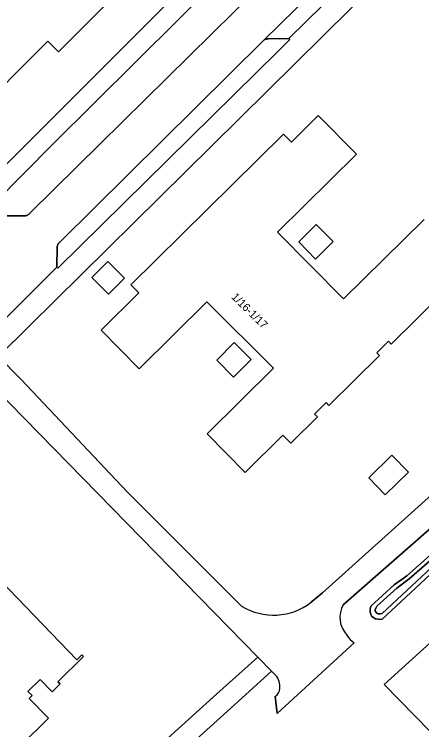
# Model space of a CAD drawing. Extents: x 162788 to 163838, y 385791 to 386523.
# Drawn here: x 163092.2 to 163143.1, y 386015.9 to 386105.3 of the extents above; entities that cross this region are included whole.
import ezdxf

# ---------------------------------------------------------------- set-up
doc = ezdxf.new("R2010")
doc.units = 0
for name, color, linetype in [('IMGEO_Berm_groen', 7, 'Continuous'), ('IMGEO_Erf', 7, 'Continuous'), ('IMGEO_Grasland_overig', 7, 'Continuous'), ('IMGEO_Groenvoorziening', 7, 'Continuous'), ('IMGEO_Hek', 7, 'Continuous'), ('IMGEO_Oever', 7, 'Continuous'), ('IMGEO_Pand', 7, 'Continuous'), ('IMGEO_Pand_nummerreeks', 7, 'Continuous'), ('IMGEO_Parkeervlak_open', 7, 'Continuous'), ('IMGEO_Rijbaan_lokaal_gesloten', 7, 'Continuous'), ('IMGEO_Voetpad_halfverhard', 7, 'Continuous'), ('IMGEO_Waterloop', 7, 'Continuous'), ('IMGEO_Woonerf_gesloten', 7, 'Continuous'), ('IMGEO_Woonerf_open', 7, 'Continuous')]:
    doc.layers.add(name, color=color, linetype=linetype)

msp = doc.modelspace()

# ---------------------------------------------------------------- linework, layer by layer
at = {"layer": 'IMGEO_Berm_groen'}
for points in [[(163117.963, 386109.833), (163097.035, 386089.065), (163082.472, 386074.358)], [(163091.029, 386080.088), (163093.415, 386080.108), (163093.492, 386080.104), (163093.569, 386080.106), (163093.646, 386080.114), (163093.721, 386080.13), (163093.795, 386080.151), (163093.867, 386080.179), (163093.937, 386080.212), (163094.003, 386080.252), (163094.066, 386080.296), (163094.124, 386080.346), (163094.179, 386080.401), (163094.228, 386080.46), (163102.959, 386089.088), (163122.487, 386108.369)]]:
    msp.add_lwpolyline(points, dxfattribs=at)
msp.add_lwpolyline([(163125.212, 386100.685), (163126.659, 386102.115), (163126.525, 386102.25), (163123.979, 386102.211), (163123.89, 386102.211), (163123.802, 386102.203), (163123.714, 386102.186), (163123.629, 386102.162), (163123.546, 386102.129), (163123.467, 386102.089), (163123.392, 386102.042), (163097.956, 386076.871), (163097.891, 386076.815), (163097.831, 386076.753), (163097.776, 386076.687), (163097.728, 386076.616), (163097.685, 386076.542), (163097.648, 386076.464), (163097.618, 386076.383), (163097.595, 386076.301), (163097.579, 386076.216), (163097.552, 386073.701), (163097.687, 386073.563)], close=True, dxfattribs=at)
at = {"layer": 'IMGEO_Erf'}
for points in [[(163047.932, 386111.375), (163063.284, 386095.753), (163064.785, 386094.225), (163081.598, 386077.116), (163079.514, 386075.045), (163075.814, 386078.831), (163062.665, 386092.122), (163061.26, 386090.73), (163077.652, 386074.193), (163078.625, 386073.903), (163090.945, 386086.246), (163109.567, 386104.883), (163137.817, 386133.231)], [(163144.69, 386116.333), (163116.889, 386088.826), (163094.139, 386066.379), (163090.229, 386062.548), (163093.084, 386059.675), (163106.347, 386045.615), (163117.907, 386034.052), (163120.625, 386031.361)], [(163105.221, 386108.078), (163097.748, 386100.603), (163096.425, 386101.925), (163086.649, 386092.147), (163084.686, 386094.11), (163079.63, 386089.054), (163076.992, 386091.691), (163076.292, 386090.991), (163073.29, 386093.993), (163073.99, 386094.693), (163069.539, 386099.143), (163070.229, 386099.833), (163068.902, 386101.16), (163068.212, 386100.47), (163060.737, 386107.943)], [(163145.83, 386070.54), (163139.3, 386064.088), (163138.953, 386064.438), (163137.507, 386063.009), (163137.853, 386062.658), (163131.536, 386056.417), (163131.19, 386056.767), (163129.743, 386055.338), (163130.09, 386054.987), (163126.763, 386051.7), (163125.779, 386052.696), (163121.082, 386048.054), (163116.31, 386052.871), (163124.617, 386061.079), (163116.284, 386069.342), (163107.849, 386061.007), (163103.083, 386065.83), (163107.785, 386070.475), (163106.801, 386071.471), (163125.865, 386090.318), (163126.854, 386089.317), (163130.198, 386092.621), (163134.963, 386087.798), (163125.119, 386078.071), (163133.366, 386069.724), (163143.424, 386079.662)], [(163129.316, 386031.834), (163130.711, 386032.995), (163156.731, 386056.38), (163168.437, 386066.688), (163193.001, 386088.975)], [(163122.643, 386025), (163088.018, 386060.382), (163078.994, 386051.539), (163082.592, 386051.498)], [(163083.877, 386047.013), (163077.501, 386040.771), (163078.117, 386040.121), (163082.342, 386044.263), (163082.601, 386043.999), (163081.98, 386043.39), (163100.049, 386024.635), (163100.685, 386025.264), (163100.884, 386025.064), (163097.686, 386021.901), (163097.949, 386021.634), (163096.965, 386020.661), (163095.449, 386022.194), (163093.939, 386020.701), (163094.444, 386020.19), (163094.075, 386019.826), (163096.492, 386017.373), (163085.965, 386006.999)], [(163017.319, 385930.66), (163017.729, 385931.02), (163049.154, 385958.577), (163094.983, 386000), (163117.539, 386020.387), (163122.643, 386025)]]:
    msp.add_lwpolyline(points, dxfattribs=at)
for points in [[(163132.041, 386076.88), (163129.874, 386074.708), (163127.777, 386076.862), (163129.94, 386079.033)], [(163101.922, 386072.392), (163103.931, 386074.377), (163105.989, 386072.295), (163103.98, 386070.31)], [(163121.809, 386062.144), (163119.615, 386059.957), (163117.538, 386062.084), (163119.713, 386064.262)], [(163141.454, 386048.102), (163138.549, 386045.273), (163136.502, 386047.374), (163139.407, 386050.204)]]:
    msp.add_lwpolyline(points, close=True, dxfattribs=at)
msp.add_arc((163124.628, 386037.886), 7.655, 238.4692, 307.7612, dxfattribs=at)
at = {"layer": 'IMGEO_Grasland_overig'}
for points in [[(163105.896, 385959.534), (163111.404, 385963.758), (163130.396, 385976.293), (163134.062, 385978.713), (163159.928, 385999.607), (163159.543, 386000), (163138.447, 386021.548), (163206.371, 386083.102), (163206.676, 386083.379), (163205.132, 386083.984), (163204.985, 386084.042), (163200.984, 386088.924), (163199.323, 386090.951), (163185.549, 386078.284), (163151.762, 386047.67), (163133.296, 386031.516)], [(163153.289, 386044.004), (163148.997, 386039.8), (163138.145, 386029.699), (163137.723, 386029.721), (163137.336, 386029.787), (163136.909, 386030.048), (163136.805, 386030.22), (163136.703, 386030.604), (163136.703, 386030.967), (163136.754, 386031.335), (163139.702, 386033.993), (163141.245, 386035.148), (163145.656, 386039.012), (163151.533, 386044.911), (163153.619, 386046.984), (163166.13, 386058.037), (163180.769, 386071.382), (163186.623, 386076.52), (163193.122, 386082.894), (163194.705, 386084.249), (163196.048, 386085.124)], [(163134.7, 386026.782), (163125.061, 386017.943), (163124.832, 386020.084)], [(163124.87, 386022.725), (163124.372, 386023.234), (163119.271, 386018.624), (163098.66, 386000), (163052.327, 385958.135), (163019.493, 385929.004)]]:
    msp.add_lwpolyline(points, dxfattribs=at)
for centre, radius, start, end in [((163136.215, 386029.958), 3.309, 151.90734, 222.69125), ((163136.2, 386029.175), 2.824, 211.14826, 237.92213), ((163123.263, 386021.308), 2.142, 353.61215, 41.39921), ((163124.063, 386021.173), 1.333, 305.23176, 355.57931)]:
    msp.add_arc(centre, radius, start, end, dxfattribs=at)
at = {"layer": 'IMGEO_Groenvoorziening'}
msp.add_lwpolyline([(163250.444, 386051.706), (163235.031, 386068.8), (163224.12, 386071.151), (163212.227, 386083.36), (163211.761, 386083.838), (163211.088, 386083.548), (163209.338, 386081.658), (163206.676, 386083.379), (163206.371, 386083.102), (163138.447, 386021.548), (163159.543, 386000), (163159.928, 385999.607), (163178.242, 386000), (163195.252, 386000.365)], close=True, dxfattribs=at)
at = {"layer": 'IMGEO_Hek'}
msp.add_lwpolyline([(163159.928, 385999.607), (163159.543, 386000), (163138.447, 386021.548), (163206.371, 386083.102), (163209.628, 386080.994), (163212.227, 386083.36)], dxfattribs=at)
at = {"layer": 'IMGEO_Oever'}
for points in [[(163148.646, 386040.168), (163138.178, 386030.424), (163137.93, 386030.383), (163137.692, 386030.39), (163137.563, 386030.434), (163137.295, 386030.735), (163137.289, 386030.896), (163137.378, 386031.12), (163137.526, 386031.346), (163140.025, 386033.6), (163141.565, 386034.753), (163146.004, 386038.641)], [(163145.656, 386039.012), (163141.245, 386035.148), (163139.702, 386033.993), (163136.754, 386031.335), (163136.703, 386030.967), (163136.703, 386030.604), (163136.805, 386030.22), (163136.909, 386030.048), (163137.336, 386029.787), (163137.723, 386029.721), (163138.145, 386029.699), (163148.997, 386039.8)]]:
    msp.add_lwpolyline(points, dxfattribs=at)
at = {"layer": 'IMGEO_Pand'}
for points in [[(163060.737, 386107.943), (163068.212, 386100.47), (163068.902, 386101.16), (163070.229, 386099.833), (163069.539, 386099.143), (163073.99, 386094.693), (163073.29, 386093.993), (163076.292, 386090.991), (163076.992, 386091.691), (163079.63, 386089.054), (163084.686, 386094.11), (163086.649, 386092.147), (163096.425, 386101.925), (163097.748, 386100.603), (163105.221, 386108.078)], [(163143.424, 386079.662), (163133.366, 386069.724), (163125.119, 386078.071), (163134.963, 386087.798), (163130.198, 386092.621), (163126.854, 386089.317), (163125.865, 386090.318), (163106.801, 386071.471), (163107.785, 386070.475), (163103.083, 386065.83), (163107.849, 386061.007), (163116.284, 386069.342), (163124.617, 386061.079), (163116.31, 386052.871), (163121.082, 386048.054), (163125.779, 386052.696), (163126.763, 386051.7), (163130.09, 386054.987), (163129.743, 386055.338), (163131.19, 386056.767), (163131.536, 386056.417), (163137.853, 386062.658), (163137.507, 386063.009), (163138.953, 386064.438), (163139.3, 386064.088), (163145.83, 386070.54)], [(163085.965, 386006.999), (163096.492, 386017.373), (163094.075, 386019.826), (163094.444, 386020.19), (163093.939, 386020.701), (163095.449, 386022.194), (163096.965, 386020.661), (163097.949, 386021.634), (163097.686, 386021.901), (163100.884, 386025.064), (163100.685, 386025.264), (163100.049, 386024.635), (163081.98, 386043.39)]]:
    msp.add_lwpolyline(points, dxfattribs=at)
for points in [[(163129.94, 386079.033), (163127.777, 386076.862), (163129.874, 386074.708), (163132.041, 386076.88)], [(163101.922, 386072.392), (163103.98, 386070.31), (163105.989, 386072.295), (163103.931, 386074.377)], [(163121.809, 386062.144), (163119.713, 386064.262), (163117.538, 386062.084), (163119.615, 386059.957)], [(163136.502, 386047.374), (163138.549, 386045.273), (163141.454, 386048.102), (163139.407, 386050.204)]]:
    msp.add_lwpolyline(points, close=True, dxfattribs=at)
at = {"layer": 'IMGEO_Parkeervlak_open'}
msp.add_lwpolyline([(163135.116, 386110.686), (163135.122, 386113.292), (163135.142, 386113.385), (163135.17, 386113.476), (163135.206, 386113.565), (163135.249, 386113.65), (163135.299, 386113.731), (163135.356, 386113.808), (163135.419, 386113.879), (163123.392, 386102.042), (163123.467, 386102.089), (163123.546, 386102.129), (163123.629, 386102.162), (163123.714, 386102.186), (163123.802, 386102.203), (163123.89, 386102.211), (163123.979, 386102.211), (163126.525, 386102.25)], close=True, dxfattribs=at)
at = {"layer": 'IMGEO_Rijbaan_lokaal_gesloten'}
for points in [[(163193.001, 386088.975), (163168.437, 386066.688), (163156.731, 386056.38), (163130.711, 386032.995), (163129.316, 386031.834)], [(163120.625, 386031.361), (163117.907, 386034.052), (163106.347, 386045.615), (163093.084, 386059.675), (163090.229, 386062.548), (163088.018, 386060.382), (163122.643, 386025), (163124.372, 386023.234), (163124.87, 386022.725)], [(163133.296, 386031.516), (163151.762, 386047.67)], [(163124.832, 386020.084), (163125.061, 386017.943), (163134.7, 386026.782)]]:
    msp.add_lwpolyline(points, dxfattribs=at)
for centre, radius, start, end in [((163124.628, 386037.886), 7.655, 238.4692, 307.7612), ((163136.215, 386029.958), 3.309, 151.90734, 222.69125), ((163136.2, 386029.175), 2.824, 211.14826, 237.92213), ((163123.263, 386021.308), 2.142, 353.61215, 41.39921), ((163124.063, 386021.173), 1.333, 305.23176, 355.57931)]:
    msp.add_arc(centre, radius, start, end, dxfattribs=at)
at = {"layer": 'IMGEO_Voetpad_halfverhard'}
msp.add_lwpolyline([(163098.66, 386000), (163119.271, 386018.624), (163124.372, 386023.234), (163122.643, 386025), (163117.539, 386020.387), (163094.983, 386000), (163049.154, 385958.577), (163017.729, 385931.02), (163017.319, 385930.66)], dxfattribs=at)
at = {"layer": 'IMGEO_Waterloop'}
msp.add_lwpolyline([(163146.004, 386038.641), (163141.565, 386034.753), (163140.025, 386033.6), (163137.526, 386031.346), (163137.378, 386031.12), (163137.289, 386030.896), (163137.295, 386030.735), (163137.563, 386030.434), (163137.692, 386030.39), (163137.93, 386030.383), (163138.178, 386030.424), (163148.646, 386040.168)], dxfattribs=at)
at = {"layer": 'IMGEO_Woonerf_gesloten'}
for points in [[(163137.817, 386133.231), (163109.567, 386104.883), (163090.945, 386086.246)], [(163033.75, 386006.932), (163059.673, 386032.606), (163072.634, 386045.307), (163078.994, 386051.539), (163088.018, 386060.382), (163090.229, 386062.548), (163094.139, 386066.379), (163116.889, 386088.826), (163144.69, 386116.333)], [(163135.116, 386110.686), (163126.525, 386102.25), (163126.659, 386102.115), (163125.212, 386100.685), (163097.687, 386073.563), (163097.552, 386073.701), (163090.455, 386066.592)], [(163082.472, 386074.358), (163097.035, 386089.065), (163117.963, 386109.833)]]:
    msp.add_lwpolyline(points, dxfattribs=at)
at = {"layer": 'IMGEO_Woonerf_open'}
for points in [[(163090.455, 386066.592), (163097.552, 386073.701), (163097.579, 386076.216), (163097.595, 386076.301), (163097.618, 386076.383), (163097.648, 386076.464), (163097.685, 386076.542), (163097.728, 386076.616), (163097.776, 386076.687), (163097.831, 386076.753), (163097.891, 386076.815), (163097.956, 386076.871), (163123.392, 386102.042), (163135.419, 386113.879)], [(163122.487, 386108.369), (163102.959, 386089.088), (163094.228, 386080.46), (163094.179, 386080.401), (163094.124, 386080.346), (163094.066, 386080.296), (163094.003, 386080.252), (163093.937, 386080.212), (163093.867, 386080.179), (163093.795, 386080.151), (163093.721, 386080.13), (163093.646, 386080.114), (163093.569, 386080.106), (163093.492, 386080.104), (163093.415, 386080.108), (163091.029, 386080.088)]]:
    msp.add_lwpolyline(points, dxfattribs=at)

# ---------------------------------------------------------------- texts
at = {"layer": 'IMGEO_Pand_nummerreeks'}
msp.add_text('1/16-1/17', height=1, rotation=315.39025, dxfattribs=at).set_placement((163119.274, 386069.884))

doc.saveas('drawing.dxf')
